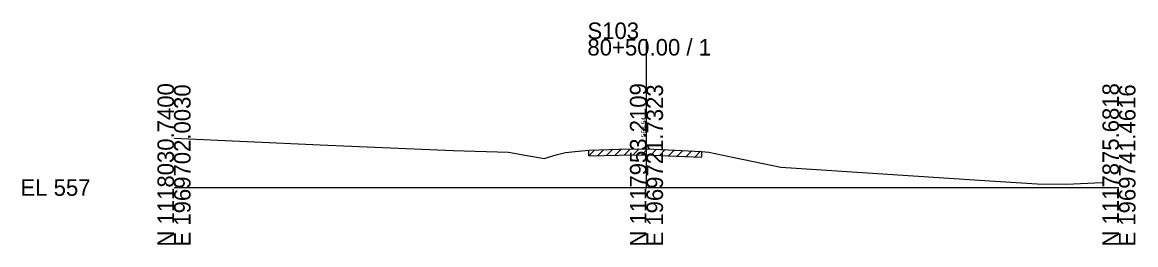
# Model space of a CAD drawing. Extents: x -26 to 163, y -10 to 45020.
# Drawn here: x -25.7 to 162.8, y 39490.3 to 39528 of the extents above; entities that cross this region are included whole.
import ezdxf

# ---------------------------------------------------------------- set-up
doc = ezdxf.new("R2010")
doc.units = 0
for name, color, linetype in [('RD_GPK_XS_Cell', 7, 'Continuous'), ('RD_XS_ExGround', 7, 'Continuous'), ('RD_XS_ExPaveRet', 7, 'Continuous'), ('RD_XS_TX_Elev_EX', 7, 'Continuous')]:
    doc.layers.add(name, color=color, linetype=linetype)

msp = doc.modelspace()

# ---------------------------------------------------------------- linework, layer by layer
at = {"layer": 'RD_GPK_XS_Cell'}
for p, q in [((80, 39500), (80, 39525.17)), ((0, 39500), (80, 39500)), ((80, 39500), (160, 39500))]:
    msp.add_line(p, q, dxfattribs=at)
at = {"layer": 'RD_XS_ExGround'}
for p, q in [((0, 39508.39), (24.76, 39507.21)), ((24.76, 39507.21), (47.29, 39506.28)), ((47.29, 39506.28), (56.62, 39505.97)), ((56.62, 39505.97), (59.46, 39505.5)), ((59.46, 39505.5), (62.68, 39504.93)), ((62.68, 39504.93), (64.72, 39505.52)), ((64.72, 39505.52), (66.29, 39505.94)), ((66.29, 39505.94), (67.94, 39506.1)), ((67.94, 39506.1), (70.22, 39506.35)), ((70.22, 39506.35), (75.39, 39506.48)), ((75.39, 39506.48), (79.23, 39506.57)), ((79.23, 39506.57), (80, 39506.54)), ((80, 39506.54), (83.68, 39506.4)), ((83.68, 39506.4), (89.33, 39506.13)), ((89.33, 39506.13), (90.53, 39505.99)), ((90.53, 39505.99), (94.85, 39505.07)), ((94.85, 39505.07), (102.75, 39503.47)), ((102.75, 39503.47), (136.39, 39501.23)), ((136.39, 39501.23), (146.14, 39500.63)), ((146.14, 39500.63), (151.05, 39500.6)), ((151.05, 39500.6), (157.18, 39500.86))]:
    msp.add_line(p, q, dxfattribs=at)
at = {"layer": 'RD_XS_ExPaveRet'}
for p, q in [((70.22, 39505.35), (71.24, 39506.38)), ((70.22, 39505.35), (70.22, 39506.35)), ((70.22, 39505.35), (75.39, 39505.48)), ((71.72, 39505.39), (72.74, 39506.41)), ((73.22, 39505.43), (74.24, 39506.45)), ((74.72, 39505.46), (75.74, 39506.49)), ((75.39, 39505.48), (79.23, 39505.57)), ((76.22, 39505.5), (77.24, 39506.53)), ((77.72, 39505.54), (78.74, 39506.56)), ((79.22, 39505.57), (80.18, 39506.54)), ((79.23, 39505.57), (80, 39505.54)), ((80, 39505.54), (83.68, 39505.4)), ((80.72, 39505.51), (81.68, 39506.48)), ((82.22, 39505.45), (83.18, 39506.42)), ((83.68, 39505.4), (89.33, 39505.13)), ((83.72, 39505.39), (84.67, 39506.35)), ((85.22, 39505.32), (86.17, 39506.28)), ((86.72, 39505.25), (87.67, 39506.21)), ((88.22, 39505.18), (89.17, 39506.14)), ((89.33, 39506.13), (89.33, 39505.13))]:
    msp.add_line(p, q, dxfattribs=at)

# ---------------------------------------------------------------- texts
at = {"layer": 'RD_GPK_XS_Cell'}
for s, p in [('S103', (70, 39525.17)), ('80+50.00 / 1', (70, 39522.37)), ('EL 557', (-26, 39498.6))]:
    msp.add_text(s, height=2.8, dxfattribs=at).set_placement(p)
for s, p in [('N 1118030.7400', (0, 39490)), ('E 1969702.0030', (2.8, 39490)), ('N 1117953.2109', (80, 39490)), ('E 1969721.7323', (82.8, 39490)), ('N 1117875.6818', (160, 39490)), ('E 1969741.4616', (162.8, 39490))]:
    msp.add_text(s, height=2.8, rotation=90, dxfattribs=at).set_placement(p)
at = {"layer": 'RD_XS_TX_Elev_EX'}
msp.add_text('563.54', height=0.8, rotation=90, dxfattribs=at).set_placement((79.9, 39508.54))

doc.saveas('drawing.dxf')
